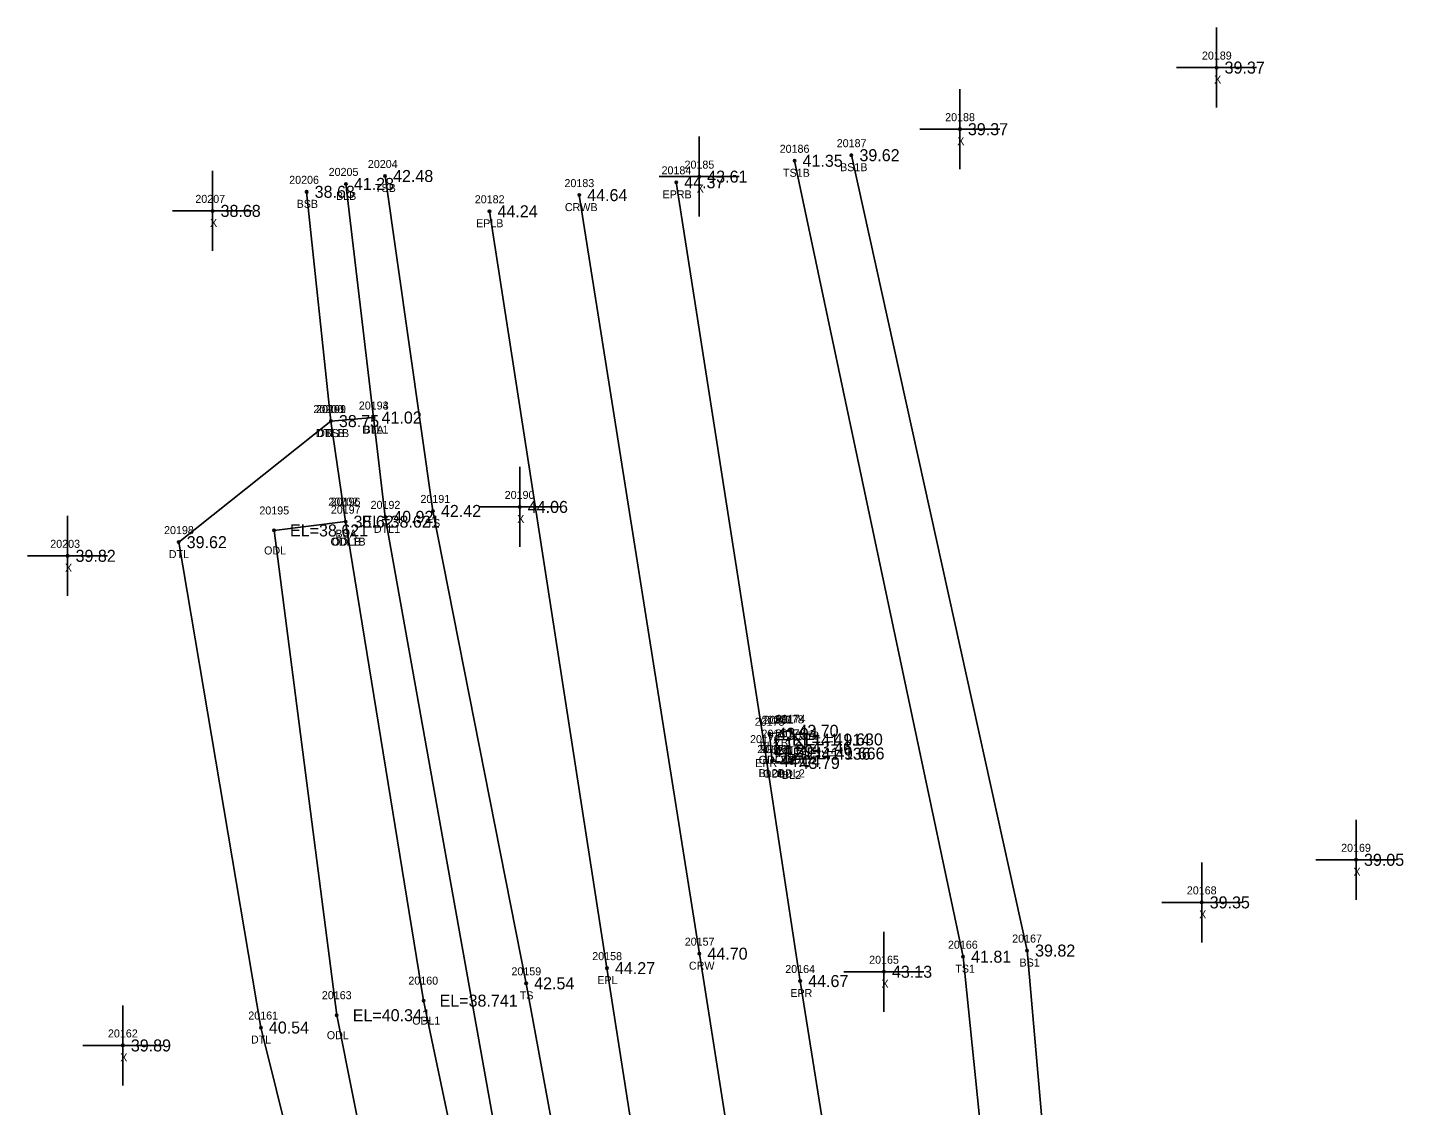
# Model space of a CAD drawing. Extents: x 2619569 to 2620117, y 784503 to 785150.
# Drawn here: x 2619719.2 to 2619891.2, y 785014.8 to 785149.6 of the extents above; entities that cross this region are included whole.
import ezdxf

# ---------------------------------------------------------------- set-up
doc = ezdxf.new("R2010")
doc.units = 0
for name, color, linetype in [('RD_DTM_BkLn1', 7, 'Continuous'), ('RD_DTM_BkLn2', 7, 'Continuous'), ('RD_DTM_BkLn_txCode', 7, 'Continuous'), ('RD_EX_H2O', 7, 'Continuous'), ('RD_EX_H2O_txCode', 7, 'Continuous'), ('RD_EX_Misc', 7, 'Continuous'), ('RD_EX_Misc_txCode', 7, 'Continuous'), ('RD_EX_Road', 7, 'Continuous'), ('RD_EX_Road_txCode', 7, 'Continuous'), ('RD_EX_TX_H2O_ELEV', 7, 'Continuous'), ('RD_EX_TX_Misc_ELEV', 7, 'Continuous'), ('RD_EX_TX_Road_ELEV', 7, 'Continuous'), ('RD_HC_Survey_ELEV', 7, 'Continuous'), ('RD_HC_Survey_txCode', 7, 'Continuous'), ('RD_SMD_Locator', 7, 'Continuous')]:
    doc.layers.add(name, color=color, linetype=linetype)

msp = doc.modelspace()

# ---------------------------------------------------------------- linework, layer by layer
at = {"layer": 'RD_DTM_BkLn1'}
msp.add_line((2619762.47, 785100.82), (2619759.01, 785130.02), dxfattribs=at)
for points in [[(2619832.4, 784847.12), (2619818.36, 784937.35), (2619803.19, 785033.82), (2619788.17, 785128.62)], [(2619812.27, 785057.88), (2619814.71, 785057.66), (2619816.25, 785059.57), (2619814.56, 785061.67), (2619811.94, 785061.3), (2619812.27, 785057.88)]]:
    msp.add_lwpolyline(points, dxfattribs=at)
at = {"layer": 'RD_DTM_BkLn2'}
for points in [[(2619858.56, 784858.85), (2619845.67, 784939.8), (2619836.14, 785033.44), (2619815.08, 785132.91)], [(2619863.71, 784859.84), (2619852.26, 784941.11), (2619844.14, 785034.21), (2619822.19, 785133.61)], [(2619819.74, 784845.33), (2619814.01, 784845.92), (2619808.4, 784862.96), (2619799.16, 784934.37), (2619781.54, 785030.11), (2619769.89, 785089.15), (2619763.91, 785131.01)], [(2619758.97, 785087.81), (2619757.14, 785100.38), (2619754.11, 785129.03)]]:
    msp.add_lwpolyline(points, dxfattribs=at)
at = {"layer": 'RD_EX_H2O'}
for points in [[(2619772.64, 784911.68), (2619772.05, 784929.46), (2619748.39, 785024.59), (2619738.12, 785085.25), (2619757.14, 785100.38)], [(2619791.73, 784933.03), (2619763.93, 785088.41), (2619762.47, 785100.82), (2619757.14, 785100.38)], [(2619777.15, 784906.8), (2619776.97, 784930.35), (2619757.87, 785026.13), (2619750.03, 785086.71), (2619758.97, 785087.81)], [(2619818.98, 784834.06), (2619808.97, 784842.56), (2619802.24, 784862.11), (2619788.78, 784932.49), (2619768.72, 785027.95), (2619758.97, 785087.81)], [(2619812.77, 785060.55), (2619814.35, 785060.6), (2619814.56, 785058.85), (2619812.83, 785058.81), (2619812.77, 785060.55)]]:
    msp.add_lwpolyline(points, dxfattribs=at)
at = {"layer": 'RD_EX_Misc'}
for p, q in [((2619867.82, 785139.56), (2619867.82, 785149.56)), ((2619862.82, 785144.56), (2619872.82, 785144.56)), ((2619835.74, 785131.86), (2619835.74, 785141.86)), ((2619830.74, 785136.86), (2619840.74, 785136.86)), ((2619803.17, 785125.93), (2619803.17, 785135.93)), ((2619742.35, 785121.65), (2619742.35, 785131.65)), ((2619798.17, 785130.93), (2619808.17, 785130.93)), ((2619737.35, 785126.65), (2619747.35, 785126.65)), ((2619780.74, 785084.65), (2619780.74, 785094.65)), ((2619775.74, 785089.65), (2619785.74, 785089.65)), ((2619724.23, 785078.54), (2619724.23, 785088.54)), ((2619719.23, 785083.54), (2619729.23, 785083.54)), ((2619885.24, 785040.55), (2619885.24, 785050.55)), ((2619865.96, 785035.23), (2619865.96, 785045.23)), ((2619880.24, 785045.55), (2619890.24, 785045.55)), ((2619860.96, 785040.23), (2619870.96, 785040.23)), ((2619826.25, 785026.56), (2619826.25, 785036.56)), ((2619821.25, 785031.56), (2619831.25, 785031.56)), ((2619731.14, 785017.35), (2619731.14, 785027.35)), ((2619726.14, 785022.35), (2619736.14, 785022.35))]:
    msp.add_line(p, q, dxfattribs=at)
at = {"layer": 'RD_EX_Road'}
for points in [[(2619820.6, 784845.48), (2619829.43, 784847.3), (2619832.4, 784847.12), (2619843.47, 784848.15), (2619843.67, 784853.02), (2619841.88, 784865.21), (2619830.54, 784938.02), (2619815.78, 785030.4), (2619811.4, 785059.13), (2619800.29, 785130.22)], [(2619820.6, 784845.48), (2619806.71, 784935.63), (2619791.64, 785032.01), (2619776.96, 785126.6)]]:
    msp.add_lwpolyline(points, dxfattribs=at)
at = {"layer": 'RD_SMD_Locator'}
for centre in [(2619867.82, 785144.56), (2619835.74, 785136.86), (2619815.08, 785132.91), (2619822.19, 785133.61), (2619763.91, 785131.01), (2619803.17, 785130.93), (2619754.11, 785129.03), (2619759.01, 785130.02), (2619800.29, 785130.22), (2619788.17, 785128.62), (2619742.35, 785126.65), (2619776.96, 785126.6), (2619757.14, 785100.38), (2619757.14, 785100.38), (2619757.14, 785100.38), (2619762.47, 785100.82), (2619762.47, 785100.82), (2619780.74, 785089.65), (2619758.97, 785087.81), (2619758.97, 785087.81), (2619758.97, 785087.81), (2619763.93, 785088.41), (2619769.89, 785089.15), (2619750.03, 785086.71), (2619738.12, 785085.25), (2619724.23, 785083.54), (2619811.94, 785061.3), (2619812.77, 785060.55), (2619812.77, 785060.55), (2619814.35, 785060.6), (2619814.56, 785061.67), (2619811.4, 785059.13), (2619812.83, 785058.81), (2619814.56, 785058.85), (2619816.25, 785059.57), (2619812.27, 785057.88), (2619812.27, 785057.88), (2619814.71, 785057.66), (2619885.24, 785045.55), (2619865.96, 785040.23), (2619803.19, 785033.82), (2619836.14, 785033.44), (2619844.14, 785034.21), (2619791.64, 785032.01), (2619826.25, 785031.56), (2619781.54, 785030.11), (2619815.78, 785030.4), (2619768.72, 785027.95), (2619757.87, 785026.13), (2619748.39, 785024.59), (2619731.14, 785022.35)]:
    msp.add_circle(centre, 0.15, dxfattribs=at)

# ---------------------------------------------------------------- texts
at = {"layer": 'RD_DTM_BkLn_txCode'}
for s, p in [('20186', (2619813.22, 785133.91)), ('20187', (2619820.35, 785134.61)), ('20204', (2619761.76, 785132.01)), ('BS1B', (2619820.77, 785131.61)), ('20206', (2619751.93, 785130.03)), ('20205', (2619756.86, 785131.02)), ('TS1B', (2619813.64, 785130.91)), ('TSB', (2619762.65, 785129.01)), ('BSB', (2619752.86, 785127.03)), ('BLB', (2619757.79, 785128.02)), ('20201', (2619755.27, 785101.38)), ('20194', (2619760.63, 785101.82)), ('BS', (2619756.36, 785098.38)), ('BLA', (2619761.22, 785098.82)), ('20197', (2619757.13, 785088.81)), ('20191', (2619768.33, 785090.15)), ('TS', (2619769.09, 785087.15)), ('BSA', (2619757.7, 785085.81)), ('20175', (2619810.1, 785062.3)), ('20174', (2619812.73, 785062.67)), ('BL2', (2619813.36, 785059.67)), ('20173', (2619814.41, 785060.57)), ('20176', (2619810.42, 785058.88)), ('20171', (2619810.72, 785058.88)), ('BL2', (2619810.73, 785059.3)), ('20172', (2619812.87, 785058.66)), ('BL2', (2619815.04, 785057.57)), ('BL2A', (2619810.58, 785055.88)), ('BL2B', (2619810.6, 785055.88)), ('BL2', (2619813.5, 785055.66)), ('20166', (2619834.25, 785034.44)), ('20167', (2619842.28, 785035.21)), ('BS1', (2619843.19, 785032.21)), ('20159', (2619779.7, 785031.11)), ('TS1', (2619835.17, 785031.44)), ('TS', (2619780.74, 785028.11))]:
    msp.add_text(s, height=1, dxfattribs=at).set_placement(p)
at = {"layer": 'RD_EX_H2O_txCode'}
for s, p in [('20200', (2619754.95, 785101.38)), ('20199', (2619755.31, 785101.38)), ('20193', (2619760.63, 785101.82)), ('DTL1B', (2619755.26, 785098.38)), ('DTLB', (2619755.43, 785098.38)), ('DTL1', (2619761.06, 785098.82)), ('20195', (2619748.2, 785088.71)), ('20202', (2619756.81, 785089.81)), ('20196', (2619757.11, 785089.81)), ('20192', (2619762.1, 785089.41)), ('20198', (2619736.29, 785086.25)), ('DTL1', (2619762.52, 785086.41)), ('ODL', (2619748.79, 785083.71)), ('ODL1B', (2619757.09, 785084.81)), ('ODLB', (2619757.25, 785084.81)), ('DTL', (2619736.88, 785083.25)), ('20177', (2619810.94, 785062.55)), ('20181', (2619811.22, 785062.55)), ('20178', (2619812.51, 785062.6)), ('20180', (2619810.95, 785060.81)), ('20179', (2619812.72, 785060.85)), ('ODL2A', (2619810.59, 785057.55)), ('ODL2B', (2619810.61, 785057.55)), ('ODL2', (2619812.65, 785057.6)), ('ODL2', (2619811.14, 785055.81)), ('ODL2', (2619812.87, 785055.85)), ('20160', (2619766.82, 785029.95)), ('20163', (2619756.01, 785028.13)), ('20161', (2619746.82, 785025.59)), ('ODL1', (2619767.31, 785024.95)), ('DTL', (2619747.15, 785022.59)), ('ODL', (2619756.63, 785023.13))]:
    msp.add_text(s, height=1, dxfattribs=at).set_placement(p)
at = {"layer": 'RD_EX_Misc_txCode'}
for s, p in [('20189', (2619865.99, 785145.56)), ('X', (2619867.51, 785142.56)), ('20188', (2619833.9, 785137.86)), ('X', (2619835.42, 785134.86)), ('20185', (2619801.33, 785131.93)), ('X', (2619802.85, 785128.93)), ('20207', (2619740.2, 785127.65)), ('X', (2619742.04, 785124.65)), ('20190', (2619778.86, 785090.65)), ('X', (2619780.42, 785087.65)), ('20203', (2619722.07, 785084.54)), ('X', (2619723.91, 785081.54)), ('20169', (2619883.38, 785046.55)), ('X', (2619884.92, 785043.55)), ('20168', (2619864.1, 785041.23)), ('X', (2619865.64, 785038.23)), ('20165', (2619824.4, 785032.56)), ('X', (2619825.94, 785029.56)), ('20162', (2619729.28, 785023.35)), ('X', (2619730.82, 785020.35))]:
    msp.add_text(s, height=1, dxfattribs=at).set_placement(p)
at = {"layer": 'RD_EX_Road_txCode'}
for s, p in [('20184', (2619798.46, 785131.22)), ('EPRB', (2619798.59, 785128.22)), ('20182', (2619775.12, 785127.6)), ('EPLB', (2619775.28, 785124.6)), ('20170', (2619809.52, 785060.13)), ('EPR', (2619810.17, 785057.13)), ('20158', (2619789.8, 785033.01)), ('20164', (2619813.92, 785031.4)), ('EPL', (2619790.43, 785030.01)), ('EPR', (2619814.55, 785028.4))]:
    msp.add_text(s, height=1, dxfattribs=at).set_placement(p)
at = {"layer": 'RD_EX_TX_H2O_ELEV'}
for s, p in [('38.75', (2619758.14, 785099.63)), ('38.75', (2619758.14, 785099.63)), ('41.02', (2619763.47, 785100.07)), ('EL=38.621', (2619760.97, 785087.06)), ('EL=38.621', (2619760.97, 785087.06)), ('40.92', (2619764.93, 785087.66)), ('EL=38.621', (2619752.03, 785085.96)), ('39.62', (2619739.12, 785084.5)), ('EL=41.914', (2619814.77, 785059.8)), ('EL=41.914', (2619814.77, 785059.8)), ('EL=41.630', (2619816.35, 785059.85)), ('EL=41.936', (2619814.83, 785058.06)), ('EL=41.666', (2619816.56, 785058.1)), ('EL=38.741', (2619770.72, 785027.2)), ('EL=40.341', (2619759.87, 785025.38)), ('40.54', (2619749.39, 785023.84))]:
    msp.add_text(s, height=1.5, dxfattribs=at).set_placement(p)
at = {"layer": 'RD_EX_TX_Misc_ELEV'}
for s, p in [('39.37', (2619868.82, 785143.81)), ('39.37', (2619836.74, 785136.11)), ('39.62', (2619823.19, 785132.86)), ('41.35', (2619816.08, 785132.16)), ('42.48', (2619764.91, 785130.26)), ('43.61', (2619804.17, 785130.18)), ('38.68', (2619755.11, 785128.28)), ('41.28', (2619760.01, 785129.27)), ('38.68', (2619743.35, 785125.9)), ('38.75', (2619758.14, 785099.63)), ('41.02', (2619763.47, 785100.07)), ('42.42', (2619770.89, 785088.4)), ('44.06', (2619781.74, 785088.9)), ('38.62', (2619759.97, 785087.06)), ('39.82', (2619725.23, 785082.79)), ('43.94', (2619812.94, 785060.55)), ('43.70', (2619815.56, 785060.92)), ('44.04', (2619813.27, 785057.13)), ('44.04', (2619813.27, 785057.13)), ('43.46', (2619817.25, 785058.82)), ('43.79', (2619815.71, 785056.91)), ('39.05', (2619886.24, 785044.8)), ('39.35', (2619866.96, 785039.48)), ('39.82', (2619845.14, 785033.46)), ('41.81', (2619837.14, 785032.69)), ('43.13', (2619827.25, 785030.81)), ('42.54', (2619782.54, 785029.36)), ('39.89', (2619732.14, 785021.6))]:
    msp.add_text(s, height=1.5, dxfattribs=at).set_placement(p)
at = {"layer": 'RD_EX_TX_Road_ELEV'}
for s, p in [('44.37', (2619801.29, 785129.47)), ('44.24', (2619777.96, 785125.85)), ('44.59', (2619812.4, 785058.38)), ('44.27', (2619792.64, 785031.26)), ('44.67', (2619816.78, 785029.65))]:
    msp.add_text(s, height=1.5, dxfattribs=at).set_placement(p)
at = {"layer": 'RD_HC_Survey_ELEV'}
for s, p in [('44.64', (2619789.17, 785127.87)), ('44.70', (2619804.19, 785033.07))]:
    msp.add_text(s, height=1.5, dxfattribs=at).set_placement(p)
at = {"layer": 'RD_HC_Survey_txCode'}
for s, p in [('20183', (2619786.33, 785129.62)), ('CRWB', (2619786.38, 785126.62)), ('20157', (2619801.36, 785034.82)), ('CRW', (2619801.88, 785031.82))]:
    msp.add_text(s, height=1, dxfattribs=at).set_placement(p)

doc.saveas('drawing.dxf')
